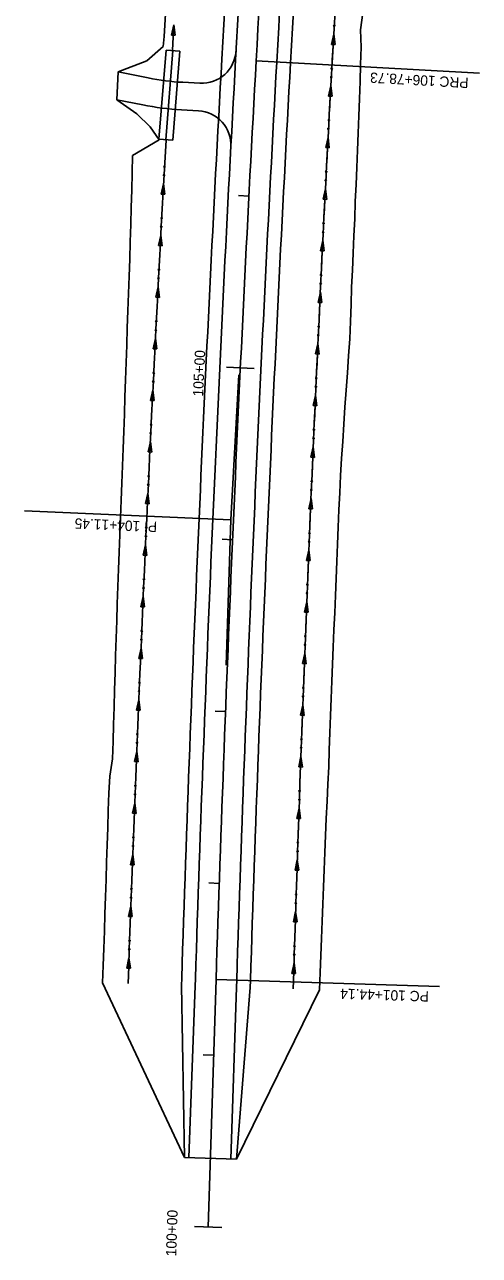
# Model space of a CAD drawing. Extents: x 1441466 to 1476381, y 2042742 to 2057194.
# Drawn here: x 1445946 to 1446211, y 2042742 to 2043457 of the extents above; entities that cross this region are included whole.
import ezdxf

# ---------------------------------------------------------------- set-up
doc = ezdxf.new("R2010")
doc.units = 0
for name, color, linetype in [('Default', 7, 'Continuous'), ('Level 43', 7, 'Continuous'), ('R_Horz Alg', 7, 'Continuous'), ('R_Horz Alg Annot', 7, 'Continuous'), ('R_Horz Alg Stationing', 7, 'Continuous'), ('R_Proposed Const Limits', 7, 'Continuous'), ('R_Proposed Road', 7, 'Continuous'), ('R_Special Ditch', 7, 'Continuous')]:
    doc.layers.add(name, color=color, linetype=linetype)

msp = doc.modelspace()

# ---------------------------------------------------------------- linework, layer by layer
at = {"layer": 'Default'}
for p, q in [((1446033.3, 2043457.1), (1446031.95, 2043451.16)), ((1446031.95, 2043451.16), (1446034.06, 2043451.05)), ((1446034.06, 2043451.05), (1446033.3, 2043457.1)), ((1446027.3, 2043364.65), (1446025.91, 2043358.72)), ((1446028.02, 2043358.6), (1446027.3, 2043364.65)), ((1446025.91, 2043358.72), (1446028.02, 2043358.6)), ((1446025.68, 2043334.66), (1446024.3, 2043328.72)), ((1446026.42, 2043328.61), (1446025.68, 2043334.66)), ((1446024.3, 2043328.72), (1446026.42, 2043328.61)), ((1446024.1, 2043304.66), (1446022.73, 2043298.72)), ((1446024.85, 2043298.61), (1446024.1, 2043304.66)), ((1446022.73, 2043298.72), (1446024.85, 2043298.61)), ((1446022.56, 2043274.66), (1446021.2, 2043268.72)), ((1446023.32, 2043268.62), (1446022.56, 2043274.66)), ((1446021.2, 2043268.72), (1446023.32, 2043268.62)), ((1446021.07, 2043244.66), (1446019.71, 2043238.72)), ((1446021.83, 2043238.62), (1446021.07, 2043244.66)), ((1446019.71, 2043238.72), (1446021.83, 2043238.62)), ((1446019.61, 2043214.66), (1446018.26, 2043208.72)), ((1446020.38, 2043208.61), (1446019.61, 2043214.66)), ((1446018.26, 2043208.72), (1446020.38, 2043208.61)), ((1446018.19, 2043184.65), (1446016.85, 2043178.71)), ((1446016.85, 2043178.71), (1446018.96, 2043178.61)), ((1446018.96, 2043178.61), (1446018.19, 2043184.65)), ((1446016.81, 2043154.65), (1446015.48, 2043148.7)), ((1446017.59, 2043148.61), (1446016.81, 2043154.65)), ((1446015.48, 2043148.7), (1446017.59, 2043148.61)), ((1446015.46, 2043124.64), (1446014.14, 2043118.69)), ((1446016.26, 2043118.6), (1446015.46, 2043124.64)), ((1446014.14, 2043118.69), (1446016.26, 2043118.6)), ((1446014.16, 2043094.63), (1446012.85, 2043088.68)), ((1446014.96, 2043088.59), (1446014.16, 2043094.63)), ((1446012.85, 2043088.68), (1446014.96, 2043088.59)), ((1446012.9, 2043064.62), (1446011.59, 2043058.67)), ((1446013.71, 2043058.58), (1446012.9, 2043064.62)), ((1446011.59, 2043058.67), (1446013.71, 2043058.58)), ((1446011.68, 2043034.61), (1446010.38, 2043028.65)), ((1446010.38, 2043028.65), (1446012.49, 2043028.57)), ((1446012.49, 2043028.57), (1446011.68, 2043034.61)), ((1446010.49, 2043004.59), (1446009.2, 2042998.64)), ((1446011.32, 2042998.55), (1446010.49, 2043004.59)), ((1446009.2, 2042998.64), (1446011.32, 2042998.55)), ((1446009.35, 2042974.57), (1446008.06, 2042968.62)), ((1446010.18, 2042968.54), (1446009.35, 2042974.57)), ((1446008.06, 2042968.62), (1446010.18, 2042968.54)), ((1446008.24, 2042944.56), (1446006.97, 2042938.6)), ((1446009.08, 2042938.52), (1446008.24, 2042944.56)), ((1446006.97, 2042938.6), (1446009.08, 2042938.52)), ((1446007.17, 2042914.54), (1446005.91, 2042908.58)), ((1446008.02, 2042908.5), (1446007.17, 2042914.54)), ((1446005.91, 2042908.58), (1446008.02, 2042908.5))]:
    msp.add_line(p, q, dxfattribs=at)
for points in [[(1446032.54, 2043442.12), (1446032.95, 2043450.04), (1446033.3, 2043457.1)], [(1446006.65, 2042899.55), (1446007, 2042909.55), (1446007.35, 2042919.57), (1446007.7, 2042929.59), (1446008.06, 2042939.6), (1446008.42, 2042949.62), (1446008.79, 2042959.63), (1446009.16, 2042969.65), (1446009.54, 2042979.66), (1446009.92, 2042989.68), (1446010.3, 2042999.69), (1446010.69, 2043009.71), (1446011.08, 2043019.72), (1446011.48, 2043029.74), (1446011.88, 2043039.75), (1446012.29, 2043049.77), (1446012.7, 2043059.78), (1446013.11, 2043069.79), (1446013.53, 2043079.81), (1446013.96, 2043089.82), (1446014.38, 2043099.83), (1446014.82, 2043109.84), (1446015.25, 2043119.86), (1446015.7, 2043129.87), (1446016.14, 2043139.88), (1446016.59, 2043149.89), (1446017.04, 2043159.91), (1446017.5, 2043169.92), (1446017.97, 2043179.93), (1446018.43, 2043189.94), (1446018.91, 2043199.95), (1446019.38, 2043209.96), (1446019.86, 2043219.97), (1446020.35, 2043229.98), (1446020.84, 2043239.99), (1446021.33, 2043250), (1446021.83, 2043260.01), (1446022.33, 2043270.02), (1446022.84, 2043280.03), (1446023.35, 2043290.04), (1446023.86, 2043300.05), (1446024.38, 2043310.05), (1446024.91, 2043320.06), (1446025.43, 2043330.07), (1446025.97, 2043340.08), (1446026.5, 2043350.09), (1446027.05, 2043360.09), (1446027.59, 2043370.1), (1446028.14, 2043380.11), (1446028.7, 2043390.11), (1446028.71, 2043390.26)], [(1446028.12, 2043379.67), (1446028.14, 2043380.11), (1446028.7, 2043390.11), (1446028.71, 2043390.26)], [(1446028.12, 2043379.63), (1446028.12, 2043379.67)], [(1446026.48, 2043349.67), (1446026.5, 2043350.09), (1446027.05, 2043360.09), (1446027.3, 2043364.65)], [(1446026.48, 2043349.64), (1446026.48, 2043349.67)], [(1446024.89, 2043319.68), (1446024.91, 2043320.06), (1446025.43, 2043330.07), (1446025.68, 2043334.66)], [(1446024.88, 2043319.64), (1446024.89, 2043319.68)], [(1446023.33, 2043289.68), (1446023.35, 2043290.04), (1446023.86, 2043300.05), (1446024.1, 2043304.66)], [(1446023.33, 2043289.64), (1446023.33, 2043289.68)], [(1446021.81, 2043259.68), (1446021.83, 2043260.01), (1446022.33, 2043270.02), (1446022.56, 2043274.66)], [(1446021.81, 2043259.64), (1446021.81, 2043259.68)], [(1446020.33, 2043229.68), (1446020.35, 2043229.98), (1446020.84, 2043239.99), (1446021.07, 2043244.66)], [(1446020.33, 2043229.64), (1446020.33, 2043229.68)], [(1446018.89, 2043199.68), (1446018.91, 2043199.95), (1446019.38, 2043209.96), (1446019.61, 2043214.66)], [(1446018.89, 2043199.64), (1446018.89, 2043199.68)], [(1446017.49, 2043169.67), (1446017.5, 2043169.92), (1446017.97, 2043179.93), (1446018.19, 2043184.65)], [(1446017.49, 2043169.63), (1446017.49, 2043169.67)], [(1446016.13, 2043139.66), (1446016.14, 2043139.88), (1446016.59, 2043149.89), (1446016.81, 2043154.65)], [(1446016.13, 2043139.63), (1446016.13, 2043139.66)], [(1446014.81, 2043109.65), (1446014.82, 2043109.84), (1446015.25, 2043119.86), (1446015.46, 2043124.64)], [(1446014.81, 2043109.62), (1446014.81, 2043109.65)], [(1446013.53, 2043079.64), (1446013.53, 2043079.81), (1446013.96, 2043089.82), (1446014.16, 2043094.63)], [(1446013.52, 2043079.61), (1446013.53, 2043079.64)], [(1446012.28, 2043049.63), (1446012.29, 2043049.77), (1446012.7, 2043059.78), (1446012.9, 2043064.62)], [(1446012.28, 2043049.59), (1446012.28, 2043049.63)], [(1446011.08, 2043019.62), (1446011.08, 2043019.72), (1446011.48, 2043029.74), (1446011.68, 2043034.61)], [(1446011.08, 2043019.58), (1446011.08, 2043019.62)], [(1446009.91, 2042989.6), (1446009.92, 2042989.68), (1446010.3, 2042999.69), (1446010.49, 2043004.59)], [(1446009.91, 2042989.56), (1446009.91, 2042989.6)], [(1446008.79, 2042959.59), (1446008.79, 2042959.63), (1446009.16, 2042969.65), (1446009.35, 2042974.57)], [(1446008.79, 2042959.55), (1446008.79, 2042959.58)], [(1446007.7, 2042929.57), (1446007.7, 2042929.59), (1446008.06, 2042939.6), (1446008.24, 2042944.56)], [(1446007.7, 2042929.53), (1446007.7, 2042929.57)], [(1446006.65, 2042899.55), (1446007, 2042909.55), (1446007.17, 2042914.54)]]:
    msp.add_lwpolyline(points, dxfattribs=at)
for centre in [(1446027.81, 2043374.65), (1446027.53, 2043369.65), (1446026.18, 2043344.66), (1446025.91, 2043339.66), (1446024.59, 2043314.66), (1446024.33, 2043309.66), (1446022.78, 2043279.66), (1446023.04, 2043284.67), (1446021.53, 2043254.67), (1446021.28, 2043249.66), (1446020.05, 2043224.66), (1446019.81, 2043219.66), (1446018.62, 2043194.66), (1446018.38, 2043189.66), (1446017.23, 2043164.65), (1446017, 2043159.65), (1446015.65, 2043129.64), (1446015.87, 2043134.65), (1446014.34, 2043099.63), (1446014.56, 2043104.64), (1446013.28, 2043074.63), (1446013.07, 2043069.62), (1446012.04, 2043044.61), (1446011.84, 2043039.61), (1446010.85, 2043014.6), (1446010.65, 2043009.59), (1446009.5, 2042979.58), (1446009.69, 2042984.58), (1446008.38, 2042949.56), (1446008.57, 2042954.57), (1446007.49, 2042924.55), (1446007.31, 2042919.54)]:
    msp.add_circle(centre, 0.375, dxfattribs=at)
at = {"layer": 'Level 43'}
for p, q in [((1446024.59, 2043390.58), (1446028.72, 2043442.42)), ((1446028.58, 2043390.27), (1446032.7, 2043442.1)), ((1446028.72, 2043442.42), (1446036.69, 2043441.78)), ((1446032.57, 2043389.95), (1446036.69, 2043441.78)), ((1446024.59, 2043390.58), (1446032.57, 2043389.95))]:
    msp.add_line(p, q, dxfattribs=at)
at = {"layer": 'R_Horz Alg'}
msp.add_line((1446053.19, 2042757.98), (1446057.8, 2042902.04), dxfattribs=at)
for centre, start, end in [((1423197.89, 2044703.4), 356.830169, 358.333333), ((1468964.38, 2042168.83), 176.830169, 178.166667)]:
    msp.add_arc(centre, 22918.31, start, end, dxfattribs=at)
at = {"layer": 'R_Horz Alg Annot'}
for q in [(1446071.02, 2043253.5), (1446063.65, 2043084.7)]:
    msp.add_line((1446066.35, 2043169.21), q, dxfattribs=at)
for points in [[(1446081.13, 2043436.12), (1446210.93, 2043428.93)], [(1446066.35, 2043169.21), (1445946.47, 2043174.45)], [(1446057.8, 2042902.04), (1446187.73, 2042897.88)]]:
    msp.add_lwpolyline(points, dxfattribs=at)
at = {"layer": 'R_Horz Alg Stationing'}
for points in [[(1446070.92, 2043357.81), (1446076.91, 2043357.5)], [(1446063.96, 2043258), (1446079.94, 2043257.24)], [(1446061.42, 2043157.98), (1446067.41, 2043157.72)], [(1446057.32, 2043058.04), (1446063.32, 2043057.81)], [(1446053.66, 2042958.08), (1446059.66, 2042957.87)], [(1446050.39, 2042858.12), (1446056.39, 2042857.93)], [(1446045.19, 2042758.23), (1446061.19, 2042757.72)]]:
    msp.add_lwpolyline(points, dxfattribs=at)
at = {"layer": 'R_Proposed Const Limits'}
for points in [[(1446000.8, 2043429.75), (1446017.61, 2043436.13), (1446027.12, 2043444.51), (1446027.62, 2043450.34), (1446028.26, 2043460.29), (1446028.87, 2043470.25), (1446029.22, 2043480.22), (1446030.38, 2043490.15), (1446031.64, 2043500.08), (1446032.09, 2043510.04), (1446032.23, 2043520.03), (1446032.34, 2043530.01), (1446032.42, 2043540), (1446033.06, 2043549.95), (1446033.72, 2043559.91), (1446034.35, 2043569.87), (1446034.94, 2043579.83), (1446035.68, 2043609.75)], [(1446069.7, 2042797.47), (1446117.91, 2042895.98), (1446118.29, 2042905.96), (1446118.67, 2042915.92), (1446119.07, 2042925.89), (1446119.46, 2042935.85), (1446119.85, 2042945.82), (1446120.24, 2042955.79), (1446120.66, 2042965.75), (1446121.06, 2042975.72), (1446121.47, 2042985.68), (1446121.91, 2042995.65), (1446122.39, 2043005.61), (1446122.87, 2043015.57), (1446123.36, 2043025.53), (1446123.56, 2043035.51), (1446123.92, 2043045.47), (1446124.34, 2043055.44), (1446124.73, 2043065.4), (1446125.14, 2043075.37), (1446125.55, 2043085.33), (1446125.96, 2043095.3), (1446126.38, 2043105.26), (1446126.8, 2043115.23), (1446127.24, 2043125.19), (1446127.62, 2043135.16), (1446128.01, 2043145.12), (1446128.4, 2043155.09), (1446128.83, 2043165.05), (1446129.25, 2043175.02), (1446129.7, 2043184.98), (1446130.23, 2043194.94), (1446130.78, 2043204.9), (1446131.43, 2043214.85), (1446132.02, 2043224.81), (1446132.75, 2043234.76), (1446133.38, 2043244.71), (1446134.18, 2043254.66), (1446134.84, 2043264.61), (1446135.65, 2043274.56), (1446135.89, 2043284.53), (1446136.43, 2043294.49), (1446136.63, 2043304.46), (1446137.17, 2043314.42), (1446137.53, 2043324.39), (1446137.93, 2043334.35), (1446138.47, 2043344.31), (1446138.7, 2043354.29), (1446139.24, 2043364.25), (1446139.73, 2043374.21), (1446140.06, 2043384.18), (1446140.49, 2043394.14), (1446140.81, 2043404.11), (1446141.17, 2043414.08), (1446141.51, 2043424.05), (1446141.86, 2043434.03), (1446142.23, 2043444.05), (1446141.77, 2043454.11), (1446143.09, 2043464.08)], [(1446039.39, 2042798.44), (1445991.85, 2042900.01), (1445992.18, 2042910.02), (1445992.54, 2042920.05), (1445992.86, 2042930.07), (1445993.19, 2042940.09), (1445993.51, 2042950.12), (1445993.83, 2042960.14), (1445994.15, 2042970.17), (1445994.49, 2042980.19), (1445994.81, 2042990.21), (1445995.14, 2043000.24), (1445995.47, 2043010.26), (1445995.93, 2043020.28), (1445997.65, 2043030.25), (1445997.93, 2043040.27), (1445998.21, 2043050.3), (1445998.5, 2043060.32), (1445998.79, 2043070.35), (1445999.09, 2043080.37), (1445999.4, 2043090.4), (1445999.71, 2043100.42), (1446000.01, 2043110.44), (1446000.37, 2043120.47), (1446000.75, 2043130.49), (1446001.06, 2043140.51), (1446001.45, 2043150.53), (1446001.82, 2043160.56), (1446002.16, 2043170.58), (1446002.55, 2043180.6), (1446003.06, 2043190.62), (1446003.45, 2043200.64), (1446003.79, 2043210.66), (1446004.12, 2043220.69), (1446004.47, 2043230.71), (1446004.82, 2043240.73), (1446005.14, 2043250.76), (1446005.49, 2043260.78), (1446005.83, 2043270.8), (1446006.17, 2043280.83), (1446006.53, 2043290.85), (1446006.89, 2043300.88), (1446007.24, 2043310.9), (1446007.62, 2043320.92), (1446007.89, 2043330.95), (1446008.17, 2043340.98), (1446008.44, 2043351.01), (1446008.73, 2043361.04), (1446009.01, 2043371.07), (1446009.3, 2043381.09), (1446024.7, 2043390.32), (1446019.53, 2043397.8), (1446011.71, 2043405.33), (1446000.1, 2043413.57)]]:
    msp.add_lwpolyline(points, dxfattribs=at)
at = {"layer": 'R_Proposed Road'}
for p, q in [((1446000.8, 2043429.75), (1446000.1, 2043413.57)), ((1446000.8, 2043429.75), (1446018.38, 2043426.23)), ((1446038.52, 2043423.68), (1446048.39, 2043423.14)), ((1446000.1, 2043413.57), (1446015.24, 2043410.54)), ((1446037.66, 2043407.7), (1446047.52, 2043407.17)), ((1446037.68, 2042898.55), (1446037.81, 2042902.68)), ((1446045.67, 2042898.29), (1446045.81, 2042902.42)), ((1446069.66, 2042897.52), (1446069.79, 2042901.66)), ((1446077.66, 2042897.27), (1446077.79, 2042901.4)), ((1446037.68, 2042898.55), (1446039.39, 2042798.44)), ((1446045.67, 2042898.29), (1446041.99, 2042798.36)), ((1446069.66, 2042897.52), (1446066.44, 2042797.57)), ((1446069.7, 2042797.47), (1446077.66, 2042897.27))]:
    msp.add_line(p, q, dxfattribs=at)
msp.add_lwpolyline([(1446069.7, 2042797.47), (1446039.39, 2042798.44)], dxfattribs=at)
for centre, radius, start, end in [((1423197.89, 2044703.4), 22898.31, 356.830169, 357.633333), ((1423197.89, 2044703.4), 22906.31, 356.830169, 357.633333), ((1423197.89, 2044703.4), 22930.31, 356.830169, 357.633333), ((1423197.89, 2044703.4), 22938.31, 356.830169, 357.633333), ((1468964.38, 2042168.83), 22938.31, 176.830169, 178.166667), ((1468964.38, 2042168.83), 22930.31, 176.830169, 178.166667), ((1446049.47, 2043443.11), 20, 266.887, 356.84327), ((1468964.38, 2042168.83), 22906.31, 176.830169, 178.166667), ((1468964.38, 2042168.83), 22898.31, 176.830169, 178.166667), ((1446046.24, 2043565.47), 142, 258.68628, 266.887), ((1446046.24, 2043565.47), 158, 258.68628, 266.887), ((1446046.43, 2043387.2), 20, 356.95691, 86.887)]:
    msp.add_arc(centre, radius, start, end, dxfattribs=at)
at = {"layer": 'R_Special Ditch'}
for p, q in [((1446126.29, 2043451.63), (1446124.88, 2043445.71)), ((1446126.99, 2043445.58), (1446126.29, 2043451.63)), ((1446124.88, 2043445.71), (1446126.99, 2043445.58)), ((1446124.54, 2043421.65), (1446123.15, 2043415.71)), ((1446123.15, 2043415.71), (1446125.26, 2043415.6)), ((1446125.26, 2043415.6), (1446124.54, 2043421.65)), ((1446122.92, 2043391.65), (1446121.56, 2043385.71)), ((1446123.67, 2043385.6), (1446122.92, 2043391.65)), ((1446121.56, 2043385.71), (1446123.67, 2043385.6)), ((1446121.39, 2043361.65), (1446120.03, 2043355.71)), ((1446122.15, 2043355.61), (1446121.39, 2043361.65)), ((1446120.03, 2043355.71), (1446122.15, 2043355.61)), ((1446119.9, 2043331.65), (1446118.55, 2043325.71)), ((1446120.66, 2043325.61), (1446119.9, 2043331.65)), ((1446118.55, 2043325.71), (1446120.66, 2043325.61)), ((1446118.45, 2043301.65), (1446117.1, 2043295.71)), ((1446119.22, 2043295.6), (1446118.45, 2043301.65)), ((1446117.1, 2043295.71), (1446119.22, 2043295.6)), ((1446117.03, 2043271.64), (1446115.7, 2043265.7)), ((1446117.81, 2043265.6), (1446117.03, 2043271.64)), ((1446115.7, 2043265.7), (1446117.81, 2043265.6)), ((1446115.66, 2043241.64), (1446114.33, 2043235.69)), ((1446116.44, 2043235.6), (1446115.66, 2043241.64)), ((1446114.33, 2043235.69), (1446116.44, 2043235.6)), ((1446114.32, 2043211.63), (1446113, 2043205.68)), ((1446115.12, 2043205.59), (1446114.32, 2043211.63)), ((1446113, 2043205.68), (1446115.12, 2043205.59)), ((1446113.03, 2043181.62), (1446111.72, 2043175.67)), ((1446113.83, 2043175.58), (1446113.03, 2043181.62)), ((1446111.72, 2043175.67), (1446113.83, 2043175.58)), ((1446111.77, 2043151.61), (1446110.47, 2043145.66)), ((1446112.58, 2043145.57), (1446111.77, 2043151.61)), ((1446110.47, 2043145.66), (1446112.58, 2043145.57)), ((1446110.55, 2043121.59), (1446109.26, 2043115.64)), ((1446111.37, 2043115.56), (1446110.55, 2043121.59)), ((1446109.26, 2043115.64), (1446111.37, 2043115.56)), ((1446109.38, 2043091.58), (1446108.09, 2043085.62)), ((1446108.09, 2043085.62), (1446110.2, 2043085.54)), ((1446110.2, 2043085.54), (1446109.38, 2043091.58)), ((1446108.24, 2043061.56), (1446106.96, 2043055.61)), ((1446109.07, 2043055.53), (1446108.24, 2043061.56)), ((1446106.96, 2043055.61), (1446109.07, 2043055.53)), ((1446107.14, 2043031.54), (1446105.87, 2043025.59)), ((1446107.98, 2043025.51), (1446107.14, 2043031.54)), ((1446105.87, 2043025.59), (1446107.98, 2043025.51)), ((1446106.08, 2043001.52), (1446104.82, 2042995.57)), ((1446106.93, 2042995.49), (1446106.08, 2043001.52)), ((1446104.82, 2042995.57), (1446106.93, 2042995.49)), ((1446105.06, 2042971.5), (1446103.8, 2042965.54)), ((1446105.92, 2042965.47), (1446105.06, 2042971.5)), ((1446103.8, 2042965.54), (1446105.92, 2042965.47)), ((1446104.08, 2042941.48), (1446102.83, 2042935.52)), ((1446102.83, 2042935.52), (1446104.95, 2042935.45)), ((1446104.95, 2042935.45), (1446104.08, 2042941.48)), ((1446103.14, 2042911.46), (1446101.9, 2042905.49)), ((1446104.01, 2042905.43), (1446103.14, 2042911.46)), ((1446101.9, 2042905.49), (1446104.01, 2042905.43))]:
    msp.add_line(p, q, dxfattribs=at)
for points in [[(1446102.69, 2042896.47), (1446102.99, 2042906.45), (1446103.29, 2042916.43), (1446103.6, 2042926.4), (1446103.92, 2042936.38), (1446104.24, 2042946.35), (1446104.56, 2042956.33), (1446104.89, 2042966.3), (1446105.22, 2042976.28), (1446105.56, 2042986.25), (1446105.9, 2042996.23), (1446106.24, 2043006.2), (1446106.59, 2043016.17), (1446106.95, 2043026.15), (1446107.31, 2043036.12), (1446107.67, 2043046.1), (1446108.03, 2043056.07), (1446108.41, 2043066.04), (1446108.78, 2043076.02), (1446109.16, 2043085.99), (1446109.55, 2043095.96), (1446109.93, 2043105.94), (1446110.33, 2043115.91), (1446110.73, 2043125.88), (1446111.13, 2043135.86), (1446111.53, 2043145.83), (1446111.94, 2043155.8), (1446112.36, 2043165.77), (1446112.78, 2043175.74), (1446113.2, 2043185.71), (1446113.63, 2043195.69), (1446114.06, 2043205.66), (1446114.5, 2043215.63), (1446114.94, 2043225.6), (1446115.38, 2043235.57), (1446115.83, 2043245.54), (1446116.29, 2043255.51), (1446116.75, 2043265.48), (1446117.21, 2043275.45), (1446117.68, 2043285.42), (1446118.15, 2043295.39), (1446118.62, 2043305.36), (1446119.1, 2043315.33), (1446119.59, 2043325.3), (1446120.08, 2043335.27), (1446120.57, 2043345.23), (1446121.07, 2043355.2), (1446121.57, 2043365.17), (1446122.08, 2043375.14), (1446122.59, 2043385.11), (1446123.1, 2043395.07), (1446123.63, 2043405.04), (1446124.17, 2043415.01), (1446124.73, 2043424.97), (1446125.3, 2043434.94), (1446125.89, 2043444.94), (1446126.49, 2043454.94), (1446127.1, 2043464.95)], [(1446125.41, 2043436.66), (1446125.89, 2043444.94), (1446126.29, 2043451.63)], [(1446125.4, 2043436.62), (1446125.41, 2043436.66)], [(1446123.71, 2043406.67), (1446124.17, 2043415.01), (1446124.54, 2043421.65)], [(1446123.71, 2043406.63), (1446123.71, 2043406.67)], [(1446122.15, 2043376.67), (1446122.59, 2043385.11), (1446122.92, 2043391.65)], [(1446122.15, 2043376.63), (1446122.15, 2043376.67)], [(1446120.64, 2043346.67), (1446121.07, 2043355.2), (1446121.39, 2043361.65)], [(1446120.64, 2043346.63), (1446120.64, 2043346.67)], [(1446119.17, 2043316.67), (1446119.59, 2043325.3), (1446119.9, 2043331.65)], [(1446119.17, 2043316.63), (1446119.17, 2043316.67)], [(1446117.73, 2043286.66), (1446118.15, 2043295.39), (1446118.45, 2043301.65)], [(1446117.73, 2043286.63), (1446117.73, 2043286.66)], [(1446116.34, 2043256.66), (1446116.75, 2043265.48), (1446117.03, 2043271.64)], [(1446116.34, 2043256.62), (1446116.34, 2043256.66)], [(1446114.99, 2043226.65), (1446115.38, 2043235.57), (1446115.66, 2043241.64)], [(1446114.98, 2043226.61), (1446114.99, 2043226.65)], [(1446113.67, 2043196.64), (1446114.06, 2043205.66), (1446114.32, 2043211.63)], [(1446113.67, 2043196.6), (1446113.67, 2043196.64)], [(1446112.39, 2043166.63), (1446112.78, 2043175.74), (1446113.03, 2043181.62)], [(1446112.39, 2043166.59), (1446112.39, 2043166.63)], [(1446111.16, 2043136.62), (1446111.53, 2043145.83), (1446111.77, 2043151.61)], [(1446111.16, 2043136.58), (1446111.16, 2043136.62)], [(1446109.96, 2043106.61), (1446110.33, 2043115.91), (1446110.55, 2043121.59)], [(1446109.96, 2043106.57), (1446109.96, 2043106.6)], [(1446108.8, 2043076.59), (1446109.16, 2043085.99), (1446109.38, 2043091.58)], [(1446108.8, 2043076.55), (1446108.8, 2043076.59)], [(1446107.69, 2043046.57), (1446108.03, 2043056.07), (1446108.24, 2043061.56)], [(1446107.68, 2043046.53), (1446107.69, 2043046.57)], [(1446106.61, 2043016.55), (1446106.95, 2043026.15), (1446107.14, 2043031.54)], [(1446106.61, 2043016.52), (1446106.61, 2043016.55)], [(1446105.57, 2042986.53), (1446105.9, 2042996.23), (1446106.08, 2043001.52)], [(1446105.57, 2042986.5), (1446105.57, 2042986.53)], [(1446104.57, 2042956.51), (1446104.89, 2042966.3), (1446105.06, 2042971.5)], [(1446104.57, 2042956.47), (1446104.57, 2042956.51)], [(1446103.61, 2042926.49), (1446103.92, 2042936.38), (1446104.08, 2042941.48)], [(1446103.61, 2042926.45), (1446103.61, 2042926.49)], [(1446102.69, 2042896.47), (1446102.99, 2042906.45), (1446103.14, 2042911.46)]]:
    msp.add_lwpolyline(points, dxfattribs=at)
for centre in [(1446126.56, 2043456.63), (1446125.08, 2043431.65), (1446124.79, 2043426.65), (1446123.41, 2043401.65), (1446123.15, 2043396.65), (1446121.86, 2043371.66), (1446121.61, 2043366.65), (1446120.11, 2043336.65), (1446120.36, 2043341.66), (1446118.89, 2043311.65), (1446118.65, 2043306.65), (1446117.46, 2043281.65), (1446117.23, 2043276.65), (1446116.08, 2043251.64), (1446115.85, 2043246.64), (1446114.73, 2043221.64), (1446114.51, 2043216.63), (1446113.2, 2043186.62), (1446113.42, 2043191.63), (1446112.15, 2043161.62), (1446111.94, 2043156.61), (1446110.92, 2043131.6), (1446110.72, 2043126.6), (1446109.73, 2043101.59), (1446109.53, 2043096.58), (1446108.58, 2043071.57), (1446108.39, 2043066.57), (1446107.28, 2043036.55), (1446107.47, 2043041.55), (1446106.22, 2043006.53), (1446106.39, 2043011.54), (1446105.36, 2042981.52), (1446105.19, 2042976.51), (1446104.37, 2042951.49), (1446104.21, 2042946.49), (1446103.41, 2042921.47), (1446103.26, 2042916.46)]:
    msp.add_circle(centre, 0.375, dxfattribs=at)

# ---------------------------------------------------------------- texts
at = {"layer": 'R_Horz Alg Annot'}
for s, rotation, p in [('PRC 106+78.73', 176.83017, (1446204.78, 2043426.27)), ('PI 104+11.45', 177.49842, (1446023.63, 2043168.08)), ('PC 101+44.14', 178.16667, (1446181.64, 2042895.07))]:
    msp.add_text(s, height=6, rotation=rotation, dxfattribs=at).set_placement(p)
at = {"layer": 'R_Horz Alg Stationing'}
for s, rotation, p in [('105+00', 87.277, (1446050.25, 2043240.85)), ('100+00', 88.16667, (1446034.63, 2042740.92))]:
    msp.add_text(s, height=6, rotation=rotation, dxfattribs=at).set_placement(p)

doc.saveas('drawing.dxf')
